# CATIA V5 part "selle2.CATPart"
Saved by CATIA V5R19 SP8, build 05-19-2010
Part number: selle2
Bounding box of the stored display mesh (mm): x -49.165 to 133.084, y -61.383 to 66.878, z -75.031 to -6.001
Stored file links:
  G:\EU_thinkMotion\CFAO_2010\SIL_groupe1\SIL_groupe1\A reprendre\scador\monocycle\selle2.CATPart
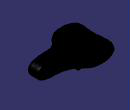
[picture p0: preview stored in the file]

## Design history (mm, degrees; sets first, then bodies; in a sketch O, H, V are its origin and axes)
Pad1: profile Sketch1, direction (0, 0, -1), length 60
Set1
  DesSubdivisionFeature1 "CATDesSubdivFeatureName"
  Plane1: type Offset, RefPlane xy-plane, Offset -20
  Sketch1 on Plane1, origin (0, 0, -20), H (1, 0, 0), V (0, 1, 0)
    point P1 (0, -7)
    line L1 (0, -7) -> (20, -7)
    line L2 (20, -7) -> (20, -12)
    line L3 (20, -12) -> (0, -12)
    line L4 (0, -12) -> (0, -7)
    point P2 (20, -7)
    point P3 (20, -12)
    point P4 (0, -12)
    point P5 (0, 7)
    point P6 (0, 12)
    line L5 (0, 12) -> (0, 7)
    point P7 (20, 7)
    line L6 (0, 7) -> (20, 7)
    point P8 (20, 12)
    line L7 (20, 7) -> (20, 12)
    line L8 (20, 12) -> (0, 12)
    distance L1 H = 7
    distance L4 L2 = 20
    distance L4 V = 0
    distance L6 L8 = 5
    horizontal: L1 H, L3 H
    vertical: L2 V, L4 V
    symmetry: P1 P5 H, P4 P6 H, L4 L5 H, P2 P7 H, L1 L6 H, P3 P8 H, L2 L7 H, L3 L8 H
Body1 (main body)
  Sketch2 on face of Pad1 from Sketch1.L3, origin (7.0552, -12, -66.5253), H (1, 0, 0), V (0, 0, 1)
    point P1 (2.9448, 1.5253)
    reference projected line E1 (-7.0552, -13.4747) -> (12.9448, -13.4747) from edge [end face of Pad1 | face of Pad1 from Sketch1.L3]
    reference projected line E2 (-7.0552, 46.5253) -> (-7.0552, -13.4747) from edge [face of Pad1 from Sketch1.L4 | face of Pad1 from Sketch1.L3]
    distance P1 E1 = 15
    distance P1 E2 = 10
  Hole1: placed by Sketch2, at (10, -12, -65) direction (0, 1, 0), diameter 8, through (limit type 3)
  Sketch3 on face of Pad1 from Sketch1.L3, origin (20, -12, -20), H (-1, 0, 0), V (0, 0, -1)
  Sketch4 on face of Pad1 from Sketch1.L3, origin (20, -12, -20), H (-1, 0, 0), V (0, 0, -1)
    arc A1 centre (10, 45.0305) radius 10 from (20, 45.0305) to (0, 45.0305) ccw
    reference projected line E1 (20, 0) -> (20, 60) from edge [face of Pad1 from Sketch1.L4 | face of Pad1 from Sketch1.L3]
    reference projected line E2 (0, 0) -> (0, 60) from edge [face of Pad1 from Sketch1.L3 | face of Pad1 from Sketch1.L2]
    line L1 (20, 45.0305) -> (20, 60)
    line L2 (20, 60) -> (0, 60)
    line L3 (0, 60) -> (0, 45.0305)
    reference projected line E3 (20, 0) -> (20, 60) from edge [face of Pad1 from Sketch1.L4 | face of Pad1 from Sketch1.L3]
    reference projected line E4 (20, 60) -> (0, 60) from edge [end face of Pad1 | face of Pad1 from Sketch1.L3]
    reference projected line E5 (0, 0) -> (0, 60) from edge [face of Pad1 from Sketch1.L3 | face of Pad1 from Sketch1.L2]
    tangency: A1 E1, A1 E2
    vertical: L1 V, L3 V
    horizontal: L2 H
    coincidence: E3 L1, L2 E4, L3 E5
  Pocket1: profile Sketch4, direction (0, 1, 0), length 60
